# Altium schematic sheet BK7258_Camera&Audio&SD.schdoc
size 436 x 215 mm
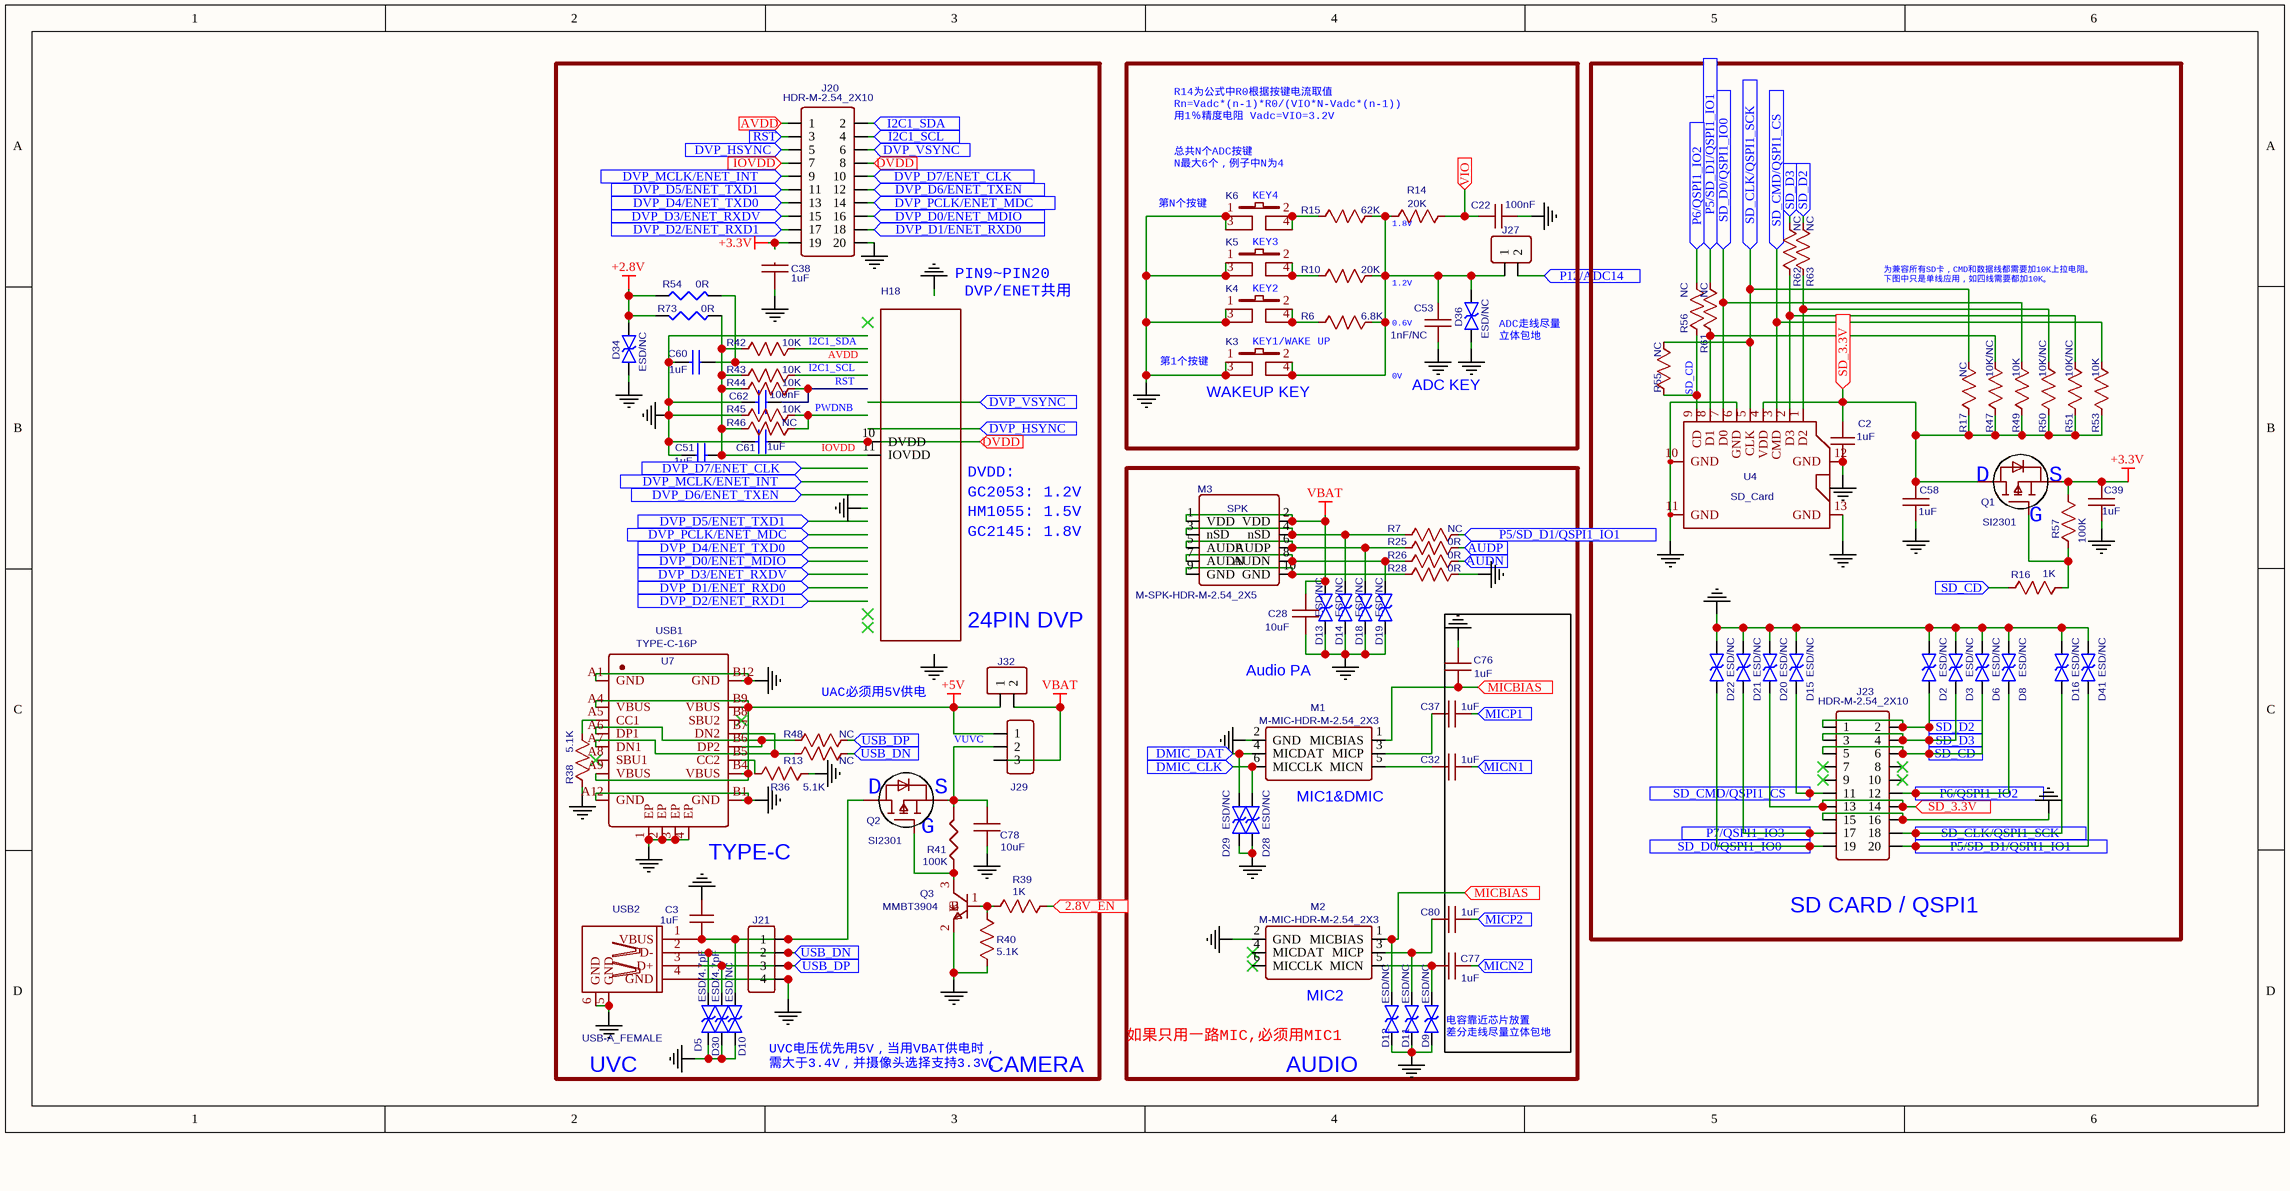
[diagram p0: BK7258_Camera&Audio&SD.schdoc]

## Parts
C2  1uF  [C0402]
C3  1uF  [C0402]
C22  100nF  [C0402]
C28  10uF  [C0603]
C32  1uF  [C0402]
C37  1uF  [C0402]
C38  1uF  [C0402]
C39  1uF  [C0402]
C51  1uF  [C0402]
C53  1nF/NC  [C0402]
C58  1uF  [C0402]
C60  1uF  [C0402]
C61  1uF  [C0402]
C62  100nF  [C0402]
C76  1uF  [C0402]
C77  1uF  [C0402]
C78  10uF  [C0603]
C80  1uF  [C0402]
D2  ESD/NC  [ESD0402]
D3  ESD/NC  [ESD0402]
D5  ESD/4.7pF  [ESD0402]
D6  ESD/NC  [ESD0402]
D8  ESD/NC  [ESD0402]
D9  ESD/NC  [ESD0402]
D10  ESD/NC  [ESD0402]
D11  ESD/NC  [ESD0402]
D12  ESD/NC  [ESD0402]
D13  ESD/NC  [ESD0402]
D14  ESD/NC  [ESD0402]
D15  ESD/NC  [ESD0402]
D16  ESD/NC  [ESD0402]
D18  ESD/NC  [ESD0402]
D19  ESD/NC  [ESD0402]
D20  ESD/NC  [ESD0402]
D21  ESD/NC  [ESD0402]
D22  ESD/NC  [ESD0402]
D28  ESD/NC  [ESD0402]
D29  ESD/NC  [ESD0402]
D30  ESD/4.7pF  [ESD0402]
D34  ESD/NC  [ESD0402]
D36  ESD/NC  [ESD0402]
D41  ESD/NC  [ESD0402]
H18  DVP 24PIN  [FPC-24PINAA]  (value not drawn)
J20  HDR-M-2.54_2X10  [HDR-M-2.54_2X10]
J21  HDR-M-2.54_1x4  [HDR-M-2.54_1X4]  (value not drawn)
J23  HDR-M-2.54_2X10  [HDR-M-2.54_2X10]
J27  HDR-M-2.54_1x2  [HDR-M-2.54_1X2]  (value not drawn)
J29  HDR-M-2.54_1x3  [HDR-M-2.54_1X3]  (value not drawn)
J32  HDR-M-2.54_1x2  [HDR-M-2.54_1X2]  (value not drawn)
K3  KEY  [4PIN_SWITCH_SMD_4.5MM]  (value not drawn)
K4  KEY  [4PIN_SWITCH_SMD_4.5MM]  (value not drawn)
K5  KEY  [4PIN_SWITCH_SMD_4.5MM]  (value not drawn)
K6  KEY  [4PIN_SWITCH_SMD_4.5MM]  (value not drawn)
M1  M-MIC-HDR-M-2.54_2X3  [M-MIC-HDR-M-2.54_2X3]
M2  M-MIC-HDR-M-2.54_2X3  [M-MIC-HDR-M-2.54_2X3]
M3  M-SPK-HDR-M-2.54_2X5  [M-SPK-HDR-M-2.54_2X5]
Q1  SI2301  [SOT-23]
Q2  SI2301  [SOT-23]
Q3  MMBT3904  [SOT-23]
R6  6.8K  [R0402]
R7  NC  [R0402]
R10  20K  [R0402]
R13  NC  [R0402]
R14  20K  [R0402]
R15  62K  [R0402]
R16  1K  [R0402]
R17  NC  [R0402]
R25  0R  [R0402]
R26  0R  [R0402]
R28  0R  [R0402]
R36  5.1K  [R0402]
R38  5.1K  [R0402]
R39  1K  [R0402]
R40  5.1K  [R0402]
R41  100K  [R0402]
R42  10K  [R0402]
R43  10K  [R0402]
R44  10K  [R0402]
R45  10K  [R0402]
R46  NC  [R0402]
R47  10K/NC  [R0402]
R48  NC  [R0402]
R49  10K  [R0402]
R50  10K/NC  [R0402]
R51  10K/NC  [R0402]
R53  10K  [R0402]
R54  0R  [R0402]
R55  NC  [R0402]
R56  NC  [R0402]
R57  100K  [R0402]
R61  NC  [R0402]
R62  NC  [R0402]
R63  NC  [R0402]
R73  0R  [R0402]
U4  SD_Card  [TF_SOCKET]
U7  TYPE-C  [TYPE-C-16P]  (value not drawn)
USB2  USB-A_FEMALE  [USB_A_FEMALE]

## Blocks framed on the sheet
AUDIO: C28 C32 C37 C76 C77 C80 D9 D11-D14 D18 D19 D28 D29 M1-M3 R7 R25 R26 R28

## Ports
2.8V_EN (in), AUDN (in), AUDP (in), AVDD (in), DMIC_CLK (in), DMIC_DAT (in), DVDD (in), DVP_D0/ENET_MDIO (in), DVP_D1/ENET_RXD0 (in), DVP_D2/ENET_RXD1 (in), DVP_D3/ENET_RXDV (in), DVP_D4/ENET_TXD0 (in), DVP_D5/ENET_TXD1 (in), DVP_D6/ENET_TXEN (in), DVP_D7/ENET_CLK (in), DVP_HSYNC (in), DVP_MCLK/ENET_INT (in), DVP_PCLK/ENET_MDC (in), DVP_VSYNC (in), I2C1_SCL (in), I2C1_SDA (in), IOVDD (in), MICBIAS (in), MICN1 (in), MICN2 (in), MICP1 (in), MICP2 (in), P5/SD_D1/QSPI1_IO1 (in), P6/QSPI1_IO2 (in), P7/QSPI1_IO3 (in), P12/ADC14 (in), RST (in), SD_3.3V (in), SD_CD (in), SD_CLK/QSPI1_SCK (in), SD_CMD/QSPI1_CS (in), SD_D0/QSPI1_IO0 (in), SD_D2 (in), SD_D3 (in), USB_DN (in), USB_DP (in), VIO (in)

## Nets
+2.8V: D34.1 R54.1 R73.2
+3.3V: C39.2 J20.19 Q1.2(S) R57.1
+5V: J29.1 J32.1 U7.A4(VBUS) U7.A9(VBUS) U7.B4(VBUS) U7.B9(VBUS)
GGND: C2.2 C3.1 C22.1 C28.2 C38.2 C39.1 C51.1 C53.1 C58.1 C60.2 C61.2 C62.2 C76.1 C78.1 D2.1 D3.1 D5.2 D6.1 D8.1 D9.2 D10.2 D11.2 D12.2 D13.2 D14.2 D15.1 D16.1 D18.2 D19.2 D20.1 D21.1 D22.1 D28.2 D29.2 D30.2 D34.2 D36.2 D41.1 J20.20 J21.4 J23.15 J23.16 K3.1 K3.3 K4.1 K4.3 K5.1 K5.3 K6.1 K6.3 M1.2(GND) M2.2(GND) Q3.2(E) R28.1 R36.1 R38.1 R40.1 R45.2 U4.6(GND) U4.10(GND) U4.11(GND) U4.12(GND) U4.13(GND) U7.1(EP) U7.2(EP) U7.3(EP) U7.4(EP) U7.A1(GND) U7.A12(GND) U7.B1(GND) U7.B12(GND) USB2.4(GND) USB2.5(GND) USB2.6(GND)
VBAT: C28.1 D13.1 J29.3 J32.2 M3.1(VDD) M3.2(VDD)
2.8V_EN: R39.2 ; port 2.8V_EN
AUDN: R26.1 ; port AUDN
AUDP: R25.1 ; port AUDP
AVDD: C60.1 R54.2
AVDD: J20.1 ; port AVDD  [a separate net that carries the same name]
DMIC_CLK: D28.1 M1.6(MICCLK) ; port DMIC_CLK
DMIC_DAT: D29.1 M1.4(MICDAT) ; port DMIC_DAT
DVDD: C61.1 H18.10(DVDD) J20.8 ; port DVDD
DVP_D0/ENET_MDIO: J20.16 ; port DVP_D0/ENET_MDIO
DVP_D1/ENET_RXD0: J20.18 ; port DVP_D1/ENET_RXD0
DVP_D2/ENET_RXD1: J20.17 ; port DVP_D2/ENET_RXD1
DVP_D3/ENET_RXDV: J20.15 ; port DVP_D3/ENET_RXDV
DVP_D4/ENET_TXD0: J20.13 ; port DVP_D4/ENET_TXD0
DVP_D5/ENET_TXD1: J20.11 ; port DVP_D5/ENET_TXD1
DVP_D6/ENET_TXEN: J20.12 ; port DVP_D6/ENET_TXEN
DVP_D7/ENET_CLK: J20.10 ; port DVP_D7/ENET_CLK
DVP_HSYNC: J20.5 ; port DVP_HSYNC
DVP_MCLK/ENET_INT: J20.9 ; port DVP_MCLK/ENET_INT
DVP_PCLK/ENET_MDC: J20.14 ; port DVP_PCLK/ENET_MDC
DVP_VSYNC: J20.6 ; port DVP_VSYNC
I2C1_SCL: J20.4 ; port I2C1_SCL
I2C1_SCL: R43.1  [a separate net that carries the same name]
I2C1_SDA: J20.2 ; port I2C1_SDA
I2C1_SDA: R42.1  [a separate net that carries the same name]
IOVDD: C51.2 H18.11(IOVDD) R42.2 R43.2 R44.2 R46.2 R73.1
IOVDD: J20.7 ; port IOVDD  [a separate net that carries the same name]
MICBIAS: C76.2 D12.1 M1.1(MICBIAS) M2.1(MICBIAS) ; port MICBIAS
MICN1: C32.1 ; port MICN1
MICN2: C77.1 ; port MICN2
MICP1: C37.1 ; port MICP1
MICP2: C80.1 ; port MICP2
P5/SD_D1/QSPI1_IO1: D41.2 J23.20 R7.1 R61.1 ; port P5/SD_D1/QSPI1_IO1
P6/QSPI1_IO2: D8.2 J23.12 R56.1 ; port P6/QSPI1_IO2
P7/QSPI1_IO3: D21.2 J23.17 ; port P7/QSPI1_IO3
P12/ADC14: J27.2 ; port P12/ADC14
PWDNB: R45.1 R46.1
RST: C62.1 R44.1
RST: J20.3 ; port RST  [a separate net that carries the same name]
SD_3.3V: C2.1 C58.2 D20.2 J23.13 J23.14 Q1.3(D) R17.2 R47.2 R49.2 R50.2 R51.2 R53.2 U4.4(VDD) ; port SD_3.3V
SD_CD: R55.2 R56.2 U4.9(CD)
SD_CD: D2.2 D3.2 D6.2 J23.1 J23.2 J23.3 J23.4 J23.5 J23.6 R16.2 R62.1 R63.1 ; port SD_D2, port SD_D3, port SD_CD  [a separate net that carries the same name]
SD_CLK/QSPI1_SCK: D16.2 J23.18 R17.1 R55.1 U4.5(CLK) ; port SD_CLK/QSPI1_SCK
SD_CMD/QSPI1_CS: D15.2 J23.11 R53.1 U4.3(CMD) ; port SD_CMD/QSPI1_CS
SD_D0/QSPI1_IO0: D22.2 J23.19 R49.1 U4.7(D0) ; port SD_D0/QSPI1_IO0
USB_DN: D5.1 J21.2 R13.1 USB2.2(D-) ; port USB_DN
USB_DP: D30.1 J21.3 R48.1 USB2.3(D+) ; port USB_DP
VIO: C22.2 R14.1 ; port VIO
VUVC: C78.2 J29.2 Q2.2(S) R41.2
NetC3_2: C3.2 D10.1 J21.1 Q2.3(D) USB2.1(VBUS)
NetC32_2: C32.2 M1.5(MICN)
NetC37_2: C37.2 M1.3(MICP)
NetC53_2: C53.2 D36.1 J27.1 K3.2 K3.4 R6.1 R10.1 R14.2 R15.1
NetC77_2: C77.2 D9.1 M2.5(MICN)
NetC80_2: C80.2 D11.1 M2.3(MICP)
NetD14_1: D14.1 M3.3(nSD) M3.4(nSD) R7.2
NetD18_1: D18.1 M3.5(AUDP) M3.6(AUDP) R25.2
NetD19_1: D19.1 M3.7(AUDN) M3.8(AUDN) R26.2
NetK4_2: K4.2 K4.4 R6.2
NetK5_2: K5.2 K5.4 R10.2
NetK6_2: K6.2 K6.4 R15.2
NetM3_9: M3.9(GND) M3.10(GND) R28.2
NetQ1_1: Q1.1(G) R16.1 R57.2
NetQ2_1: Q2.1(G) Q3.3(C) R41.1
NetQ3_1: Q3.1(B) R39.1 R40.2
NetR13_2: R13.2 U7.A7(DN1) U7.B7(DN2)
NetR36_2: R36.2 U7.B5(CC2)
NetR38_2: R38.2 U7.A5(CC1)
NetR47_1: R47.1 R61.2 U4.8(D1)
NetR48_2: R48.2 U7.A6(DP1) U7.B6(DP2)
NetR50_1: R50.1 R63.2 U4.1(D2)
NetR51_1: R51.1 R62.2 U4.2(D3)

Not connected (* = marked no-connect by the designer): J23 7* 8* 9* 10*; M2 4(MICDAT)* 6(MICCLK)*; U7 A8(SBU1)* B8(SBU2)*

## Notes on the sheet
- (near K6) R14为公式中R0根据按键电流取值
  Rn=Vadc*(n-1)*R0/(VIO*N-Vadc*(n-1))
  用1％精度电阻 Vadc=VIO=3.2V
- 总共N个ADC按键
  N最大6个，例子中N为4
- 第N个按键
- (near K6) KEY4
- (near R14) 1.8V
- PIN9~PIN20
  DVP/ENET共用
- KEY3
- KEY2
- 1.2V
- 为兼容所有SD卡，CMD和数据线都需要加10K上拉电阻。
  下图中只是单线应用，如四线需要都加10K。
- 第1个按键
- KEY1/WAKE UP
- 0.6V
- ADC走线尽量
  立体包地
- (near K3) WAKEUP KEY
- 0V
- ADC KEY
- GC2053: 1.2V
- DVDD:
- (near Q1) D
- (near Q1) S
- HM1055: 1.5V
- GC2145: 1.8V
- (near Q1) G
- 24PIN DVP
- UAC必须用5V供电
- Audio PA
- (near Q2) D
- (near Q2) S
- (near M1) MIC1&DMIC
- (near U7) TYPE-C
- (near Q2) G
- (near J23) SD CARD / QSPI1
- (near M2) MIC2
- (near D9) 电容靠近芯片放置
  差分走线尽量立体包地
- UVC
- UVC电压优先用5V，当用VBAT供电时，
  需大于3.4V，并摄像头选择支持3.3V。
- CAMERA
- 如果只用一路MIC,必须用MIC1
- Labels drawn without touching a wire or pin: GGND

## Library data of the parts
C2 C3 = 1uF: Manufacturer Part Number: 06035A101KAT2A; Manufacturer: AVX; APN: C029-0
C22 = 100nF: Manufacturer Part Number: 06035A101KAT2A; Manufacturer: AVX; APN: C029-0
C28 C78 = 10uF: Manufacturer: AVX; Manufacturer Part Number: 0805ZC105KAT2A; APN: C071-0
C32 C37-C39 C58 C76 C77 C80 = 1uF: Manufacturer: AVX; Manufacturer Part Number: 0805ZC105KAT2A; APN: C071-0
C51 C60 C61 = 1uF: Manufacturer Part Number: 08055A390JATMA; Manufacturer: AVX; APN: C012-0
C53 = 1nF/NC: Manufacturer: AVX; Manufacturer Part Number: 0805ZC105KAT2A; APN: C071-0
C62 = 100nF: Manufacturer Part Number: 08055A390JATMA; Manufacturer: AVX; APN: C012-0
D2 D3 D6 D8-D16 D18-D22 D28 D29 D34 D36 D41 = ESD/NC: Contributor: D-MAN
D5 D30 = ESD/4.7pF: Contributor: D-MAN
H18 = DVP 24PIN: Manufacturer Part Number: 0.5-24P XGXJ-H2.0 119; BOM_Manufacturer: SHOU HAN(首韩)
J20 J23 = HDR-M-2.54_2X10: Contributor: LCEDA_Lib
J21 = HDR-M-2.54_1x4: Contributor: LCEDA_Lib
J27 J32 = HDR-M-2.54_1x2: Contributor: LCEDA_Lib
J29 = HDR-M-2.54_1x3: Contributor: LCEDA_Lib
K3-K6 = KEY: BOM_Manufacturer: BOOMELE(博穆精密); Manufacturer Part: 4.5x4.5x3.8贴片
M1 M2 = M-MIC-HDR-M-2.54_2X3: Contributor: qunshan.xu
M3 = M-SPK-HDR-M-2.54_2X5: Contributor: qunshan.xu
Q1 Q2 = SI2301: Manufacturer: YONGYUTAI(永裕泰); Contributor: lcsc
Q3 = MMBT3904: Manufacturer: PANJIT International; Contributor: LCSC
R6 = 6.8K: nameAlias: Value(Ω); Contributor: LCEDA_Lib
R7 R13 R17 R46 R48 R55 R56 R61-R63 = NC: nameAlias: Value(Ω); Contributor: LCEDA_Lib
R10 R14 = 20K: nameAlias: Value(Ω); Contributor: LCEDA_Lib
R15 = 62K: nameAlias: Value(Ω); Contributor: LCEDA_Lib
R16 R39 = 1K: nameAlias: Value(Ω); Contributor: LCEDA_Lib
R25 R26 R28 = 0R: nameAlias: Value(Ω); Contributor: LCEDA_Lib
R36 R38 R40 = 5.1K: nameAlias: Value(Ω); Contributor: LCEDA_Lib
R41 = 100K: Manufacturer Part Number: RK73H2AT4752F; Manufacturer: KOA; APN: R096-0
R42-R45 R49 R53 = 10K: nameAlias: Value(Ω); Contributor: LCEDA_Lib
R47 R50 R51 = 10K/NC: nameAlias: Value(Ω); Contributor: LCEDA_Lib
R54 R73 = 0R: Manufacturer Part Number: RM73B1JT240J; Manufacturer: KOA; APN: R125-0
R57 = 100K: nameAlias: Value(Ω); Contributor: LCEDA_Lib
U4 = SD_Card: BOM_Manufacturer: SHOU HAN(首韩)
U7 = TYPE-C: Manufacturer Part: TYPE-C 16PIN 2MD(073); BOM_Manufacturer: SHOU HAN(首韩); Contributor: jian.shi1
USB2 = USB-A_FEMALE: BOM_Manufacturer: kinghelm(金航标)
